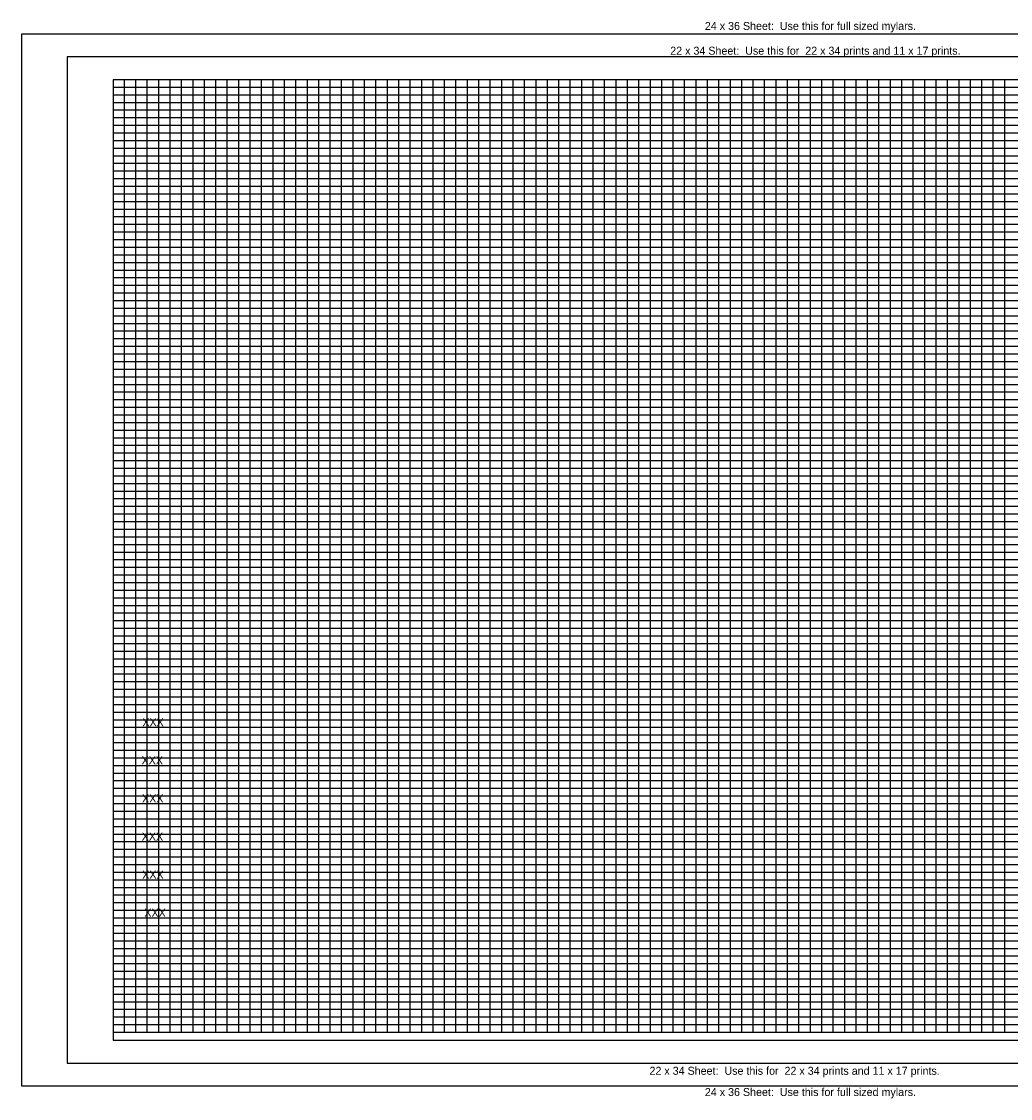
# Model space of a CAD drawing. Extents: x -3875 to -2152, y -2513 to -1536.
# Drawn here: x -3875 to -3010, y -2513 to -1571 of the extents above; entities that cross this region are included whole.
import ezdxf

# ---------------------------------------------------------------- set-up
doc = ezdxf.new("R2010")
doc.units = 0
for name, color, linetype in [('G_BORDER', 7, 'Continuous'), ('G_GRID_MAJOR', 7, 'Continuous'), ('G_GRID_MINOR', 7, 'Continuous'), ('G_SHEET_EDGE', 7, 'Continuous')]:
    doc.layers.add(name, color=color, linetype=linetype)

msp = doc.modelspace()

# ---------------------------------------------------------------- linework, layer by layer
at = {"layer": 'G_BORDER'}
msp.add_lwpolyline([(-3794.61, -2462.21), (-2494.61, -2462.21), (-2494.61, -1622.21), (-3794.61, -1622.21)], close=True, dxfattribs=at)
at = {"layer": 'G_GRID_MAJOR'}
for p, q in [((-3724.61, -2455.54), (-3724.61, -1622.21)), ((-3624.61, -2455.54), (-3624.61, -1622.21)), ((-3524.61, -2455.54), (-3524.61, -1622.21)), ((-3424.61, -2455.54), (-3424.61, -1622.21)), ((-3324.61, -2455.54), (-3324.61, -1622.21)), ((-3224.61, -2455.54), (-3224.61, -1622.21)), ((-3124.61, -2455.54), (-3124.61, -1622.21)), ((-3024.61, -2455.54), (-3024.61, -1622.21)), ((-2494.61, -1655.54), (-3794.61, -1655.54)), ((-2494.61, -1688.88), (-3794.61, -1688.88)), ((-2494.61, -1722.21), (-3794.61, -1722.21)), ((-2494.61, -1755.54), (-3794.61, -1755.54)), ((-2494.61, -1788.88), (-3794.61, -1788.88)), ((-2494.61, -1822.21), (-3794.61, -1822.21)), ((-2494.61, -1855.54), (-3794.61, -1855.54)), ((-2494.61, -1888.88), (-3794.61, -1888.88)), ((-2494.61, -1922.21), (-3794.61, -1922.21)), ((-2494.61, -1955.54), (-3794.61, -1955.54)), ((-2494.61, -1988.87), (-3794.61, -1988.87)), ((-2494.61, -2022.21), (-3794.61, -2022.21)), ((-2724.61, -2055.54), (-3794.61, -2055.54)), ((-2724.61, -2088.87), (-3794.61, -2088.87)), ((-2724.61, -2122.21), (-3794.61, -2122.21)), ((-2724.61, -2155.54), (-3794.61, -2155.54)), ((-2724.61, -2188.87), (-3794.61, -2188.87)), ((-2724.61, -2222.21), (-3794.61, -2222.21)), ((-2724.61, -2255.54), (-3794.61, -2255.54)), ((-2724.61, -2288.87), (-3794.61, -2288.87)), ((-2724.61, -2322.21), (-3794.61, -2322.21)), ((-2724.61, -2355.54), (-3794.61, -2355.54)), ((-2724.61, -2388.87), (-3794.61, -2388.87)), ((-2724.61, -2422.21), (-3794.61, -2422.21)), ((-2724.61, -2455.54), (-3794.61, -2455.54))]:
    msp.add_line(p, q, dxfattribs=at)
at = {"layer": 'G_GRID_MINOR'}
for p, q in [((-2494.61, -1628.88), (-3794.61, -1628.88)), ((-3784.61, -2455.54), (-3784.61, -1622.21)), ((-3774.61, -2455.54), (-3774.61, -1622.21)), ((-3764.61, -2455.54), (-3764.61, -1622.21)), ((-3754.61, -2455.54), (-3754.61, -1622.21)), ((-3744.61, -2455.54), (-3744.61, -1622.21)), ((-3734.61, -2455.54), (-3734.61, -1622.21)), ((-3714.61, -2455.54), (-3714.61, -1622.21)), ((-3704.61, -2455.54), (-3704.61, -1622.21)), ((-3694.61, -2455.54), (-3694.61, -1622.21)), ((-3684.61, -2455.54), (-3684.61, -1622.21)), ((-3674.61, -2455.54), (-3674.61, -1622.21)), ((-3664.61, -2455.54), (-3664.61, -1622.21)), ((-3654.61, -2455.54), (-3654.61, -1622.21)), ((-3644.61, -2455.54), (-3644.61, -1622.21)), ((-3634.61, -2455.54), (-3634.61, -1622.21)), ((-3614.61, -2455.54), (-3614.61, -1622.21)), ((-3604.61, -2455.54), (-3604.61, -1622.21)), ((-3594.61, -2455.54), (-3594.61, -1622.21)), ((-3584.61, -2455.54), (-3584.61, -1622.21)), ((-3574.61, -2455.54), (-3574.61, -1622.21)), ((-3564.61, -2455.54), (-3564.61, -1622.21)), ((-3554.61, -2455.54), (-3554.61, -1622.21)), ((-3544.61, -2455.54), (-3544.61, -1622.21)), ((-3534.61, -2455.54), (-3534.61, -1622.21)), ((-3514.61, -2455.54), (-3514.61, -1622.21)), ((-3504.61, -2455.54), (-3504.61, -1622.21)), ((-3494.61, -2455.54), (-3494.61, -1622.21)), ((-3484.61, -2455.54), (-3484.61, -1622.21)), ((-3474.61, -2455.54), (-3474.61, -1622.21)), ((-3464.61, -2455.54), (-3464.61, -1622.21)), ((-3454.61, -2455.54), (-3454.61, -1622.21)), ((-3444.61, -2455.54), (-3444.61, -1622.21)), ((-3434.61, -2455.54), (-3434.61, -1622.21)), ((-3414.61, -2455.54), (-3414.61, -1622.21)), ((-3404.61, -2455.54), (-3404.61, -1622.21)), ((-3394.61, -2455.54), (-3394.61, -1622.21)), ((-3384.61, -2455.54), (-3384.61, -1622.21)), ((-3374.61, -2455.54), (-3374.61, -1622.21)), ((-3364.61, -2455.54), (-3364.61, -1622.21)), ((-3354.61, -2455.54), (-3354.61, -1622.21)), ((-3344.61, -2455.54), (-3344.61, -1622.21)), ((-3334.61, -2455.54), (-3334.61, -1622.21)), ((-3314.61, -2455.54), (-3314.61, -1622.21)), ((-3304.61, -2455.54), (-3304.61, -1622.21)), ((-3294.61, -2455.54), (-3294.61, -1622.21)), ((-3284.61, -2455.54), (-3284.61, -1622.21)), ((-3274.61, -2455.54), (-3274.61, -1622.21)), ((-3264.61, -2455.54), (-3264.61, -1622.21)), ((-3254.61, -2455.54), (-3254.61, -1622.21)), ((-3244.61, -2455.54), (-3244.61, -1622.21)), ((-3234.61, -2455.54), (-3234.61, -1622.21)), ((-3214.61, -2455.54), (-3214.61, -1622.21)), ((-3204.61, -2455.54), (-3204.61, -1622.21)), ((-3194.61, -2455.54), (-3194.61, -1622.21)), ((-3184.61, -2455.54), (-3184.61, -1622.21)), ((-3174.61, -2455.54), (-3174.61, -1622.21)), ((-3164.61, -2455.54), (-3164.61, -1622.21)), ((-3154.61, -2455.54), (-3154.61, -1622.21)), ((-3144.61, -2455.54), (-3144.61, -1622.21)), ((-3134.61, -2455.54), (-3134.61, -1622.21)), ((-3114.61, -2455.54), (-3114.61, -1622.21)), ((-3104.61, -2455.54), (-3104.61, -1622.21)), ((-3094.61, -2455.54), (-3094.61, -1622.21)), ((-3084.61, -2455.54), (-3084.61, -1622.21)), ((-3074.61, -2455.54), (-3074.61, -1622.21)), ((-3064.61, -2455.54), (-3064.61, -1622.21)), ((-3054.61, -2455.54), (-3054.61, -1622.21)), ((-3044.61, -2455.54), (-3044.61, -1622.21)), ((-3034.61, -2455.54), (-3034.61, -1622.21)), ((-3014.61, -2455.54), (-3014.61, -1622.21)), ((-2494.61, -1635.54), (-3794.61, -1635.54)), ((-2494.61, -1642.21), (-3794.61, -1642.21)), ((-2494.61, -1648.88), (-3794.61, -1648.88)), ((-2494.61, -1662.21), (-3794.61, -1662.21)), ((-2494.61, -1668.88), (-3794.61, -1668.88)), ((-2494.61, -1675.54), (-3794.61, -1675.54)), ((-2494.61, -1682.21), (-3794.61, -1682.21)), ((-2494.61, -1695.54), (-3794.61, -1695.54)), ((-2494.61, -1702.21), (-3794.61, -1702.21)), ((-2494.61, -1708.88), (-3794.61, -1708.88)), ((-2494.61, -1715.54), (-3794.61, -1715.54)), ((-2494.61, -1728.88), (-3794.61, -1728.88)), ((-2494.61, -1735.54), (-3794.61, -1735.54)), ((-2494.61, -1742.21), (-3794.61, -1742.21)), ((-2494.61, -1748.88), (-3794.61, -1748.88)), ((-2494.61, -1762.21), (-3794.61, -1762.21)), ((-2494.61, -1768.88), (-3794.61, -1768.88)), ((-2494.61, -1775.54), (-3794.61, -1775.54)), ((-2494.61, -1782.21), (-3794.61, -1782.21)), ((-2494.61, -1795.54), (-3794.61, -1795.54)), ((-2494.61, -1802.21), (-3794.61, -1802.21)), ((-2494.61, -1808.88), (-3794.61, -1808.88)), ((-2494.61, -1815.54), (-3794.61, -1815.54)), ((-2494.61, -1828.88), (-3794.61, -1828.88)), ((-2494.61, -1835.54), (-3794.61, -1835.54)), ((-2494.61, -1842.21), (-3794.61, -1842.21)), ((-2494.61, -1848.88), (-3794.61, -1848.88)), ((-2494.61, -1862.21), (-3794.61, -1862.21)), ((-2494.61, -1868.88), (-3794.61, -1868.88)), ((-2494.61, -1875.54), (-3794.61, -1875.54)), ((-2494.61, -1882.21), (-3794.61, -1882.21)), ((-2494.61, -1895.54), (-3794.61, -1895.54)), ((-2494.61, -1902.21), (-3794.61, -1902.21)), ((-2494.61, -1908.87), (-3794.61, -1908.87)), ((-2494.61, -1915.54), (-3794.61, -1915.54)), ((-2494.61, -1928.87), (-3794.61, -1928.87)), ((-2494.61, -1935.54), (-3794.61, -1935.54)), ((-2494.61, -1942.21), (-3794.61, -1942.21)), ((-2494.61, -1948.87), (-3794.61, -1948.87)), ((-2494.61, -1962.21), (-3794.61, -1962.21)), ((-2494.61, -1968.87), (-3794.61, -1968.87)), ((-2494.61, -1975.54), (-3794.61, -1975.54)), ((-2494.61, -1982.21), (-3794.61, -1982.21)), ((-2494.61, -1995.54), (-3794.61, -1995.54)), ((-2494.61, -2002.21), (-3794.61, -2002.21)), ((-2494.61, -2008.87), (-3794.61, -2008.87)), ((-2494.61, -2015.54), (-3794.61, -2015.54)), ((-2494.61, -2028.87), (-3794.61, -2028.87)), ((-2494.61, -2035.54), (-3794.61, -2035.54)), ((-2494.61, -2042.21), (-3794.61, -2042.21)), ((-2494.61, -2048.87), (-3794.61, -2048.87)), ((-2724.61, -2062.21), (-3794.61, -2062.21)), ((-2724.61, -2068.87), (-3794.61, -2068.87)), ((-2724.61, -2075.54), (-3794.61, -2075.54)), ((-2724.61, -2082.21), (-3794.61, -2082.21)), ((-2724.61, -2095.54), (-3794.61, -2095.54)), ((-2724.61, -2102.21), (-3794.61, -2102.21)), ((-2724.61, -2108.87), (-3794.61, -2108.87)), ((-2724.61, -2115.54), (-3794.61, -2115.54)), ((-2724.61, -2128.87), (-3794.61, -2128.87)), ((-2724.61, -2135.54), (-3794.61, -2135.54)), ((-2724.61, -2142.21), (-3794.61, -2142.21)), ((-2724.61, -2148.87), (-3794.61, -2148.87)), ((-2724.61, -2162.21), (-3794.61, -2162.21)), ((-2724.61, -2168.87), (-3794.61, -2168.87)), ((-2724.61, -2175.54), (-3794.61, -2175.54)), ((-2724.61, -2182.21), (-3794.61, -2182.21)), ((-2724.61, -2195.54), (-3794.61, -2195.54)), ((-2724.61, -2202.21), (-3794.61, -2202.21)), ((-2724.61, -2208.87), (-3794.61, -2208.87)), ((-2724.61, -2215.54), (-3794.61, -2215.54)), ((-2724.61, -2228.87), (-3794.61, -2228.87)), ((-2724.61, -2235.54), (-3794.61, -2235.54)), ((-2724.61, -2242.21), (-3794.61, -2242.21)), ((-2724.61, -2248.87), (-3794.61, -2248.87)), ((-2724.61, -2262.21), (-3794.61, -2262.21)), ((-2724.61, -2268.87), (-3794.61, -2268.87)), ((-2724.61, -2275.54), (-3794.61, -2275.54)), ((-2724.61, -2282.21), (-3794.61, -2282.21)), ((-2724.61, -2295.54), (-3794.61, -2295.54)), ((-2724.61, -2302.21), (-3794.61, -2302.21)), ((-2724.61, -2308.87), (-3794.61, -2308.87)), ((-2724.61, -2315.54), (-3794.61, -2315.54)), ((-2724.61, -2328.87), (-3794.61, -2328.87)), ((-2724.61, -2335.54), (-3794.61, -2335.54)), ((-2724.61, -2342.21), (-3794.61, -2342.21)), ((-2724.61, -2348.87), (-3794.61, -2348.87)), ((-2724.61, -2362.21), (-3794.61, -2362.21)), ((-2724.61, -2368.87), (-3794.61, -2368.87)), ((-2724.61, -2375.54), (-3794.61, -2375.54)), ((-2724.61, -2382.21), (-3794.61, -2382.21)), ((-2724.61, -2395.54), (-3794.61, -2395.54)), ((-2724.61, -2402.21), (-3794.61, -2402.21)), ((-2724.61, -2408.87), (-3794.61, -2408.87)), ((-2724.61, -2415.54), (-3794.61, -2415.54)), ((-2724.61, -2428.87), (-3794.61, -2428.87)), ((-2724.61, -2435.54), (-3794.61, -2435.54)), ((-2724.61, -2442.21), (-3794.61, -2442.21)), ((-2724.61, -2448.87), (-3794.61, -2448.87))]:
    msp.add_line(p, q, dxfattribs=at)
at = {"layer": 'G_SHEET_EDGE'}
for points in [[(-2454.61, -1582.21), (-3874.61, -1582.21), (-3874.61, -2502.21), (-2454.61, -2502.21)], [(-2474.61, -1602.21), (-3834.61, -1602.21), (-3834.61, -2482.21), (-2474.61, -2482.21)]]:
    msp.add_lwpolyline(points, close=True, dxfattribs=at)

# ---------------------------------------------------------------- texts
at = {"layer": 'G_GRID_MAJOR'}
for p in [(-3768.92, -2187.62), (-3769.63, -2220.96), (-3769.2, -2254.29), (-3769.48, -2287.62), (-3769.06, -2320.96), (-3767.21, -2354.29)]:
    msp.add_text('XXX', height=7, dxfattribs=at).set_placement(p)
at = {"layer": 'G_SHEET_EDGE'}
for s, p in [('24 x 36 Sheet:  Use this for full sized mylars. ', (-3276.92, -1578.61)), ('22 x 34 Sheet:  Use this for  22 x 34 prints and 11 x 17 prints. ', (-3307.2, -1600.26)), ('22 x 34 Sheet:  Use this for  22 x 34 prints and 11 x 17 prints. ', (-3325.35, -2492.51)), ('24 x 36 Sheet:  Use this for full sized mylars. ', (-3276.92, -2511.11))]:
    msp.add_text(s, height=7, dxfattribs=at).set_placement(p)

doc.saveas('drawing.dxf')
